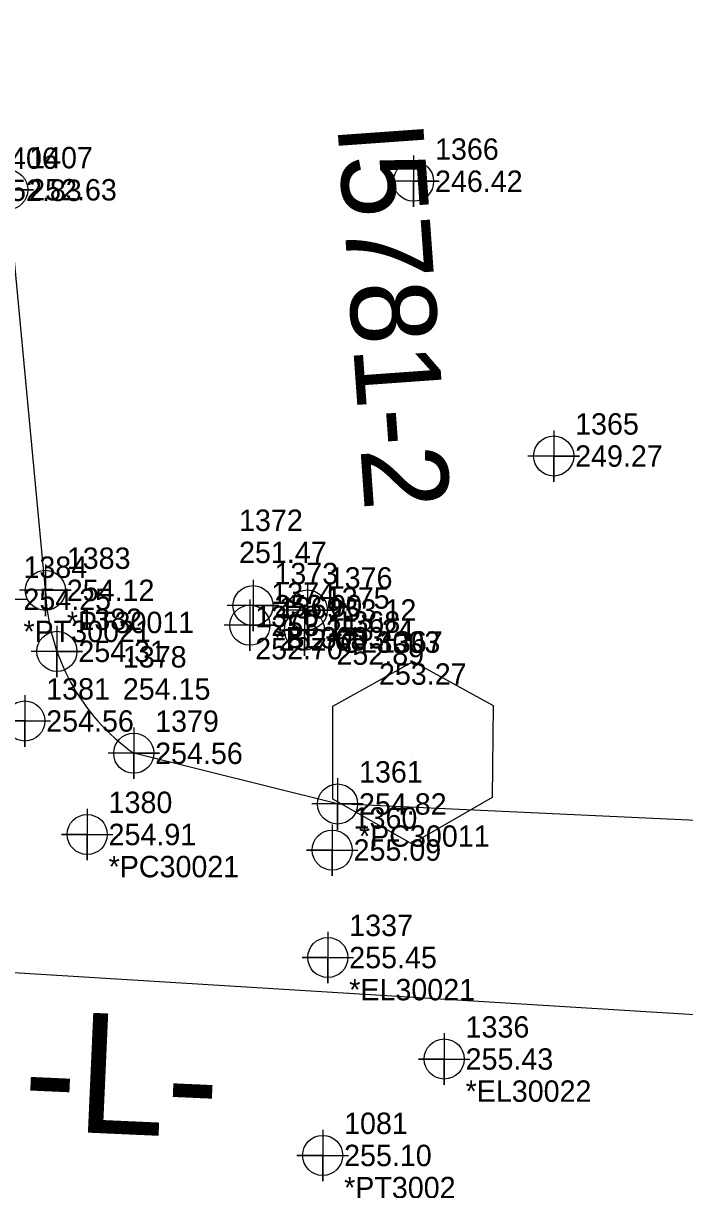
# Model space of a CAD drawing. Extents: x 2130621 to 2131998, y 642516 to 644503.
# Drawn here: x 2131261.7 to 2131338.9, y 643152.6 to 643288.8 of the extents above; entities that cross this region are included whole.
import ezdxf

# ---------------------------------------------------------------- set-up
doc = ezdxf.new("R2010")
doc.units = 0
for name, color, linetype in [('CTL Primary Horizontal and Vertical CELL', 7, 'Continuous'), ('CTL Primary Horizontal and Vertical Text', 7, 'Continuous'), ('Exist Other Culture Anchor (Guy Wire) Cogo Elevation', 7, 'Continuous'), ('Exist Other Culture Anchor (Guy Wire) Cogo Number', 7, 'Continuous'), ('Exist Other Culture Sign Cogo Elevation', 7, 'Continuous'), ('Exist Other Culture Sign Cogo Number', 7, 'Continuous'), ('Exist Roads EOP', 7, 'Continuous'), ('Exist Roads EOP Cogo Comment', 7, 'Continuous'), ('Exist Roads EOP Cogo Elevation', 7, 'Continuous'), ('Exist Roads EOP Cogo Number', 7, 'Continuous'), ('Exist Roads EOP Cogo Point CELL', 7, 'Continuous'), ('Exist Roads EOP Other Cogo Comment', 7, 'Continuous'), ('Exist Roads EOP Other Cogo Elevation', 7, 'Continuous'), ('Exist Roads EOP Other Cogo Number', 7, 'Continuous'), ('Exist Roads EOP Other Cogo Point CELL', 7, 'Continuous'), ('Exist Roads EOT Cogo Comment', 7, 'Continuous'), ('Exist Roads EOT Cogo Elevation', 7, 'Continuous'), ('Exist Roads EOT Cogo Number', 7, 'Continuous'), ('Exist Roads EOT Cogo Point CELL', 7, 'Continuous'), ('Exist Utilities Other Traffic Signal Box Cogo Elevation', 7, 'Continuous'), ('Exist Utilities Other Traffic Signal Box Cogo Number', 7, 'Continuous'), ('Exist Utilities Power Pole Cogo Elevation', 7, 'Continuous'), ('Exist Utilities Power Pole Cogo Number', 7, 'Continuous'), ('Exist Vegetation Woods Line Cogo Elevation', 7, 'Continuous'), ('Exist Vegetation Woods Line Cogo Number', 7, 'Continuous'), ('Exist Vegetation Woods Line Cogo Point CELL', 7, 'Continuous'), ('Prop Horizontal Alignment', 7, 'Continuous')]:
    doc.layers.add(name, color=color, linetype=linetype)

msp = doc.modelspace()

# ---------------------------------------------------------------- linework, layer by layer
at = {"layer": 'CTL Primary Horizontal and Vertical CELL'}
msp.add_line((2131307.12, 643203.65), (2131307.12, 643203.65), dxfattribs=at)
msp.add_lwpolyline([(2131297.82, 643209.04), (2131307.18, 643214.26), (2131316.54, 643209.11), (2131316.4, 643198.38), (2131307.04, 643192.95), (2131297.82, 643198.17)], close=True, dxfattribs=at)
at = {"layer": 'Exist Roads EOP'}
for points in [[(2131264.27, 643222.56), (2131259.88, 643269.33), (2131257.02, 643319.4), (2131254.26, 643369.65), (2131250.08, 643419.42), (2131246.15, 643469.03), (2131240.84, 643519.13), (2131234.37, 643568.56), (2131226.33, 643620.18), (2131217.03, 643668.71), (2131205.62, 643717.61), (2131192.06, 643767.26), (2131177.97, 643815.09), (2131162.29, 643862.93), (2131145.36, 643910.85), (2131126.91, 643957.29), (2131112.37, 643996.12)], [(2131447.24, 643189.53), (2131397.4, 643192.3), (2131347.72, 643195.32), (2131298.37, 643197.61), (2131274.58, 643203.53)]]:
    msp.add_lwpolyline(points, dxfattribs=at)
msp.add_ellipse((2131288.7, 643223.47), major_axis=(22.85, -8.67), ratio=0.999529, start_param=3.54142, end_param=4.459267, dxfattribs=at)
at = {"layer": 'Exist Roads EOP Cogo Point CELL'}
for points in [[(2131259.88, 643272.33), (2131259.88, 643266.33), (2131259.88, 643269.33), (2131262.88, 643269.33), (2131256.88, 643269.33)], [(2131264.27, 643225.56), (2131264.27, 643219.56), (2131264.27, 643222.56), (2131267.27, 643222.56), (2131261.27, 643222.56)], [(2131265.62, 643218.43), (2131265.62, 643212.43), (2131265.62, 643215.43), (2131268.62, 643215.43), (2131262.62, 643215.43)], [(2131274.58, 643206.53), (2131274.58, 643200.53), (2131274.58, 643203.53), (2131277.58, 643203.53), (2131271.58, 643203.53)], [(2131298.37, 643200.61), (2131298.37, 643194.61), (2131298.37, 643197.61), (2131301.37, 643197.61), (2131295.37, 643197.61)]]:
    msp.add_lwpolyline(points, dxfattribs=at)
for centre in [(2131259.88, 643269.33), (2131264.27, 643222.56), (2131265.62, 643215.43), (2131274.58, 643203.53), (2131298.37, 643197.61)]:
    msp.add_circle(centre, 2.34, dxfattribs=at)
at = {"layer": 'Exist Roads EOP Other Cogo Point CELL'}
for points in [[(2131288.5, 643223.77), (2131288.5, 643217.77), (2131288.5, 643220.77), (2131291.5, 643220.77), (2131285.5, 643220.77)], [(2131294.84, 643223.26), (2131294.84, 643217.26), (2131294.84, 643220.26), (2131297.84, 643220.26), (2131291.84, 643220.26)], [(2131288.14, 643221.48), (2131288.14, 643215.48), (2131288.14, 643218.48), (2131291.14, 643218.48), (2131285.14, 643218.48)], [(2131294.5, 643220.91), (2131294.5, 643214.91), (2131294.5, 643217.91), (2131297.5, 643217.91), (2131291.5, 643217.91)]]:
    msp.add_lwpolyline(points, dxfattribs=at)
for centre in [(2131288.5, 643220.77), (2131294.84, 643220.26), (2131288.14, 643218.48), (2131294.5, 643217.91)]:
    msp.add_circle(centre, 2.34, dxfattribs=at)
at = {"layer": 'Exist Roads EOT Cogo Point CELL'}
for points in [[(2131259.21, 643224.51), (2131259.21, 643218.51), (2131259.21, 643221.51), (2131256.21, 643221.51), (2131262.21, 643221.51)], [(2131261.87, 643210.3), (2131261.87, 643204.3), (2131261.87, 643207.3), (2131258.87, 643207.3), (2131264.87, 643207.3)], [(2131269.15, 643197.05), (2131269.15, 643191.05), (2131269.15, 643194.05), (2131266.15, 643194.05), (2131272.15, 643194.05)], [(2131297.74, 643195.23), (2131297.74, 643189.23), (2131297.74, 643192.23), (2131294.74, 643192.23), (2131300.74, 643192.23)], [(2131297.23, 643182.68), (2131297.23, 643176.68), (2131297.23, 643179.68), (2131294.23, 643179.68), (2131300.23, 643179.68)], [(2131310.81, 643170.83), (2131310.81, 643164.83), (2131310.81, 643167.83), (2131307.81, 643167.83), (2131313.81, 643167.83)], [(2131296.63, 643159.57), (2131296.63, 643153.57), (2131296.63, 643156.57), (2131293.63, 643156.57), (2131299.63, 643156.57)]]:
    msp.add_lwpolyline(points, dxfattribs=at)
for centre in [(2131261.87, 643207.3), (2131269.15, 643194.05), (2131297.74, 643192.23), (2131297.23, 643179.68), (2131310.81, 643167.83), (2131296.63, 643156.57)]:
    msp.add_circle(centre, 2.34, dxfattribs=at)
at = {"layer": 'Exist Vegetation Woods Line Cogo Point CELL'}
for points in [[(2131307.24, 643273.33), (2131307.24, 643267.33), (2131307.24, 643270.33), (2131310.24, 643270.33), (2131304.24, 643270.33)], [(2131323.59, 643241.24), (2131323.59, 643235.24), (2131323.59, 643238.24), (2131326.59, 643238.24), (2131320.59, 643238.24)]]:
    msp.add_lwpolyline(points, dxfattribs=at)
for centre in [(2131307.24, 643270.33), (2131323.59, 643238.24)]:
    msp.add_circle(centre, 2.34, dxfattribs=at)
at = {"layer": 'Prop Horizontal Alignment'}
msp.add_line((2131251.47, 643178.51), (2131445.73, 643166.48), dxfattribs=at)

# ---------------------------------------------------------------- texts
at = {"layer": 'CTL Primary Horizontal and Vertical Text'}
msp.add_text('I5781-2', height=10, rotation=274.0871, dxfattribs=at).set_placement((2131298.33, 643276.94))
at = {"layer": 'Exist Other Culture Anchor (Guy Wire) Cogo Elevation'}
for s, p in [('251.47', (2131286.87, 643225.74)), ('253.27', (2131303.2, 643211.53))]:
    msp.add_text(s, height=2.5, dxfattribs=at).set_placement(p)
at = {"layer": 'Exist Other Culture Anchor (Guy Wire) Cogo Number'}
for s, p in [('1372', (2131286.87, 643229.49)), ('1367', (2131303.2, 643215.28))]:
    msp.add_text(s, height=2.5, dxfattribs=at).set_placement(p)
at = {"layer": 'Exist Other Culture Sign Cogo Elevation'}
for s, p in [('252.89', (2131298.24, 643213.86)), ('254.15', (2131273.31, 643209.79))]:
    msp.add_text(s, height=2.5, dxfattribs=at).set_placement(p)
at = {"layer": 'Exist Other Culture Sign Cogo Number'}
for s, p in [('1368', (2131298.24, 643217.61)), ('1378', (2131273.31, 643213.54))]:
    msp.add_text(s, height=2.5, dxfattribs=at).set_placement(p)
at = {"layer": 'Exist Roads EOP Cogo Comment'}
for s, p in [('*PT30011', (2131266.77, 643217.56)), ('*PC30011', (2131300.87, 643192.61))]:
    msp.add_text(s, height=2.5, dxfattribs=at).set_placement(p)
at = {"layer": 'Exist Roads EOP Cogo Elevation'}
for s, p in [('252.63', (2131262.38, 643268.08)), ('254.12', (2131266.77, 643221.31)), ('254.31', (2131268.12, 643214.18)), ('254.56', (2131277.08, 643202.28)), ('254.82', (2131300.87, 643196.36))]:
    msp.add_text(s, height=2.5, dxfattribs=at).set_placement(p)
at = {"layer": 'Exist Roads EOP Cogo Number'}
for s, p in [('1407', (2131262.38, 643271.83)), ('1383', (2131266.77, 643225.06)), ('1382', (2131268.12, 643217.93)), ('1379', (2131277.08, 643206.03)), ('1361', (2131300.87, 643200.11))]:
    msp.add_text(s, height=2.5, dxfattribs=at).set_placement(p)
at = {"layer": 'Exist Roads EOP Other Cogo Comment'}
for s, p in [('*BL3003', (2131291, 643215.77)), ('*CL3003', (2131297.34, 643215.26))]:
    msp.add_text(s, height=2.5, dxfattribs=at).set_placement(p)
at = {"layer": 'Exist Roads EOP Other Cogo Elevation'}
for s, p in [('253.00', (2131291, 643219.52)), ('253.12', (2131297.34, 643219.01)), ('253.11', (2131290.64, 643217.23)), ('253.24', (2131297, 643216.66))]:
    msp.add_text(s, height=2.5, dxfattribs=at).set_placement(p)
at = {"layer": 'Exist Roads EOP Other Cogo Number'}
for s, p in [('1373', (2131291, 643223.27)), ('1376', (2131297.34, 643222.76)), ('1374', (2131290.64, 643220.98)), ('1375', (2131297, 643220.41))]:
    msp.add_text(s, height=2.5, dxfattribs=at).set_placement(p)
at = {"layer": 'Exist Roads EOT Cogo Comment'}
for s, p in [('*PT30021', (2131261.71, 643216.51)), ('*PC30021', (2131271.65, 643189.05)), ('*EL30021', (2131299.73, 643174.68)), ('*EL30022', (2131313.31, 643162.83)), ('*PT3002', (2131299.13, 643151.57))]:
    msp.add_text(s, height=2.5, dxfattribs=at).set_placement(p)
at = {"layer": 'Exist Roads EOT Cogo Elevation'}
for s, p in [('252.83', (2131258.29, 643268.02)), ('254.25', (2131261.71, 643220.26)), ('254.56', (2131264.37, 643206.05)), ('254.91', (2131271.65, 643192.8)), ('255.09', (2131300.24, 643190.98)), ('255.45', (2131299.73, 643178.43)), ('255.43', (2131313.31, 643166.58)), ('255.10', (2131299.13, 643155.32))]:
    msp.add_text(s, height=2.5, dxfattribs=at).set_placement(p)
at = {"layer": 'Exist Roads EOT Cogo Number'}
for s, p in [('1406', (2131258.29, 643271.77)), ('1384', (2131261.71, 643224.01)), ('1381', (2131264.37, 643209.8)), ('1380', (2131271.65, 643196.55)), ('1360', (2131300.24, 643194.73)), ('1337', (2131299.73, 643182.18)), ('1336', (2131313.31, 643170.33)), ('1081', (2131299.13, 643159.07))]:
    msp.add_text(s, height=2.5, dxfattribs=at).set_placement(p)
at = {"layer": 'Exist Utilities Other Traffic Signal Box Cogo Elevation'}
msp.add_text('252.68', height=2.5, dxfattribs=at).set_placement((2131291.51, 643215.53))
at = {"layer": 'Exist Utilities Other Traffic Signal Box Cogo Number'}
msp.add_text('1369', height=2.5, dxfattribs=at).set_placement((2131291.51, 643219.28))
at = {"layer": 'Exist Utilities Power Pole Cogo Elevation'}
msp.add_text('252.70', height=2.5, dxfattribs=at).set_placement((2131288.76, 643214.5))
at = {"layer": 'Exist Utilities Power Pole Cogo Number'}
msp.add_text('1370', height=2.5, dxfattribs=at).set_placement((2131288.76, 643218.25))
at = {"layer": 'Exist Vegetation Woods Line Cogo Elevation'}
for s, p in [('246.42', (2131309.74, 643269.08)), ('249.27', (2131326.09, 643236.99))]:
    msp.add_text(s, height=2.5, dxfattribs=at).set_placement(p)
at = {"layer": 'Exist Vegetation Woods Line Cogo Number'}
for s, p in [('1366', (2131309.74, 643272.83)), ('1365', (2131326.09, 643240.74))]:
    msp.add_text(s, height=2.5, dxfattribs=at).set_placement(p)
at = {"layer": 'Prop Horizontal Alignment'}
msp.add_text('-L-', height=14, rotation=357.4317, dxfattribs=at).set_placement((2131261.47, 643159.58))

doc.saveas('drawing.dxf')
